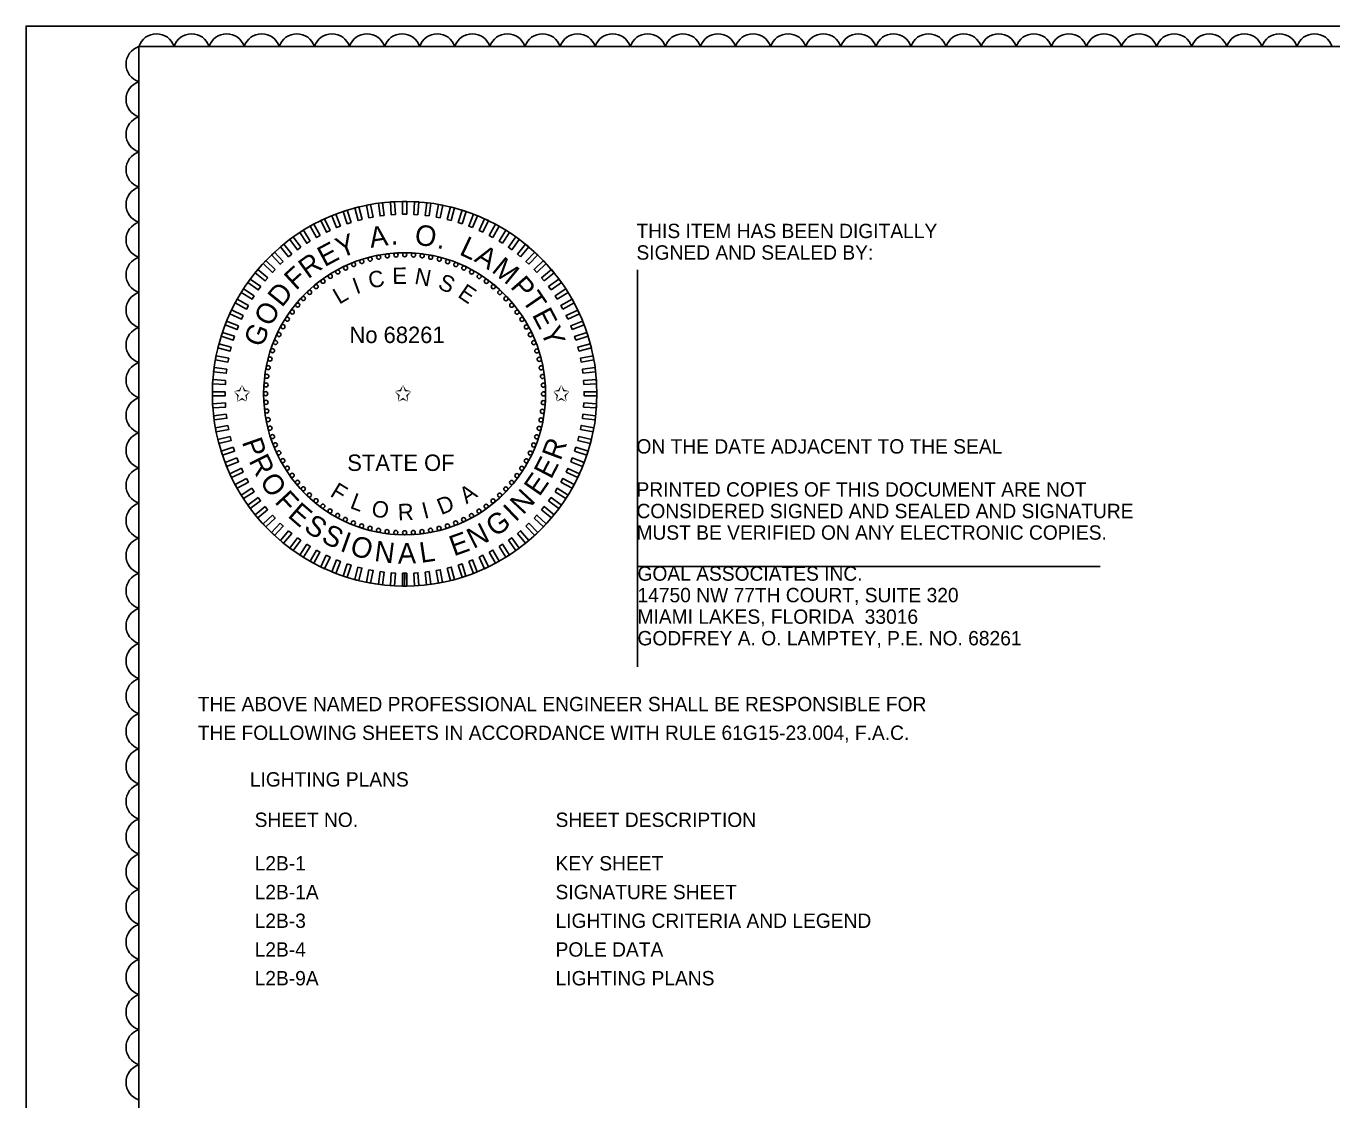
# Model space of a CAD drawing. Extents: x -811.3 to -790.1, y -2211.9 to -2188.9.
# Drawn here: x -811.34 to -804.97, y -2194.13 to -2188.9 of the extents above; entities that cross this region are included whole.
import ezdxf

# ---------------------------------------------------------------- set-up
doc = ezdxf.new("R2010")
doc.units = 0
for name, color, linetype in [('Cloud_dp', 7, 'Continuous'), ('Logo_dp', 7, 'Continuous'), ('NonPlottingEle_dp', 7, 'Continuous'), ('PlotBorder_dp', 7, 'Continuous'), ('ScratchEle_dp', 7, 'Continuous'), ('SheetBorder_dp', 7, 'Continuous'), ('TextMisc', 7, 'Continuous'), ('TextNotes', 7, 'Continuous')]:
    doc.layers.add(name, color=color, linetype=linetype)

msp = doc.modelspace()

# ---------------------------------------------------------------- linework, layer by layer
at = {"layer": 'Cloud_dp'}
for centre, start, end in [((-810.7002, -2189.0276), 17.5, 162.5), ((-810.5291, -2189.0276), 17.5, 162.5), ((-810.358, -2189.0276), 17.5, 162.5), ((-810.1868, -2189.0276), 17.5, 162.5), ((-810.0157, -2189.0276), 17.5, 162.5), ((-809.8446, -2189.0276), 17.5, 162.5), ((-809.6735, -2189.0276), 17.5, 162.5), ((-809.5024, -2189.0276), 17.5, 162.5), ((-809.3312, -2189.0276), 17.5, 162.5), ((-809.1601, -2189.0276), 17.5, 162.5), ((-808.989, -2189.0276), 17.5, 162.5), ((-808.8179, -2189.0276), 17.5, 162.5), ((-808.6467, -2189.0276), 17.5, 162.5), ((-808.4756, -2189.0276), 17.5, 162.5), ((-808.3045, -2189.0276), 17.5, 162.5), ((-808.1334, -2189.0276), 17.5, 162.5), ((-807.9622, -2189.0276), 17.5, 162.5), ((-807.7911, -2189.0276), 17.5, 162.5), ((-807.62, -2189.0276), 17.5, 162.5), ((-807.4489, -2189.0276), 17.5, 162.5), ((-807.2778, -2189.0276), 17.5, 162.5), ((-807.1066, -2189.0276), 17.5, 162.5), ((-806.9355, -2189.0276), 17.5, 162.5), ((-806.7644, -2189.0276), 17.5, 162.5), ((-806.5933, -2189.0276), 17.5, 162.5), ((-806.4221, -2189.0276), 17.5, 162.5), ((-806.251, -2189.0276), 17.5, 162.5), ((-806.0799, -2189.0276), 17.5, 162.5), ((-805.9088, -2189.0276), 17.5, 162.5), ((-805.7377, -2189.0276), 17.5, 162.5), ((-805.5665, -2189.0276), 17.5, 162.5), ((-805.3954, -2189.0276), 17.5, 162.5), ((-805.2243, -2189.0276), 17.5, 162.5), ((-805.0532, -2189.0276), 17.5, 162.5), ((-810.7588, -2189.0862), 107.5, 252.5), ((-810.7588, -2189.2573), 107.5, 252.5), ((-810.7588, -2189.4284), 107.5, 252.5), ((-810.7588, -2189.5996), 107.5, 252.5), ((-810.7588, -2189.7707), 107.5, 252.5), ((-810.7588, -2189.9418), 107.5, 252.5), ((-810.7588, -2190.1129), 107.5, 252.5), ((-810.7588, -2190.2841), 107.5, 252.5), ((-810.7588, -2190.4552), 107.5, 252.5), ((-810.7588, -2190.6263), 107.5, 252.5), ((-810.7588, -2190.7974), 107.5, 252.5), ((-810.7588, -2190.9685), 107.5, 252.5), ((-810.7588, -2191.1397), 107.5, 252.5), ((-810.7588, -2191.3108), 107.5, 252.5), ((-810.7588, -2191.4819), 107.5, 252.5), ((-810.7588, -2191.653), 107.5, 252.5), ((-810.7588, -2191.8242), 107.5, 252.5), ((-810.7588, -2191.9953), 107.5, 252.5), ((-810.7588, -2192.1664), 107.5, 252.5), ((-810.7588, -2192.3375), 107.5, 252.5), ((-810.7588, -2192.5087), 107.5, 252.5), ((-810.7588, -2192.6798), 107.5, 252.5), ((-810.7588, -2192.8509), 107.5, 252.5), ((-810.7588, -2193.022), 107.5, 252.5), ((-810.7588, -2193.1931), 107.5, 252.5), ((-810.7588, -2193.3643), 107.5, 252.5), ((-810.7588, -2193.5354), 107.5, 252.5), ((-810.7588, -2193.7065), 107.5, 252.5), ((-810.7588, -2193.8776), 107.5, 252.5), ((-810.7588, -2194.0488), 107.5, 252.5)]:
    msp.add_arc(centre, 0.0897, start, end, dxfattribs=at)
at = {"layer": 'Logo_dp'}
for p, q in [((-809.5001, -2191.6301), (-809.5003, -2191.5676)), ((-809.4901, -2191.6301), (-809.4903, -2191.5676)), ((-809.4801, -2191.6301), (-809.4803, -2191.5676))]:
    msp.add_line(p, q, dxfattribs=at)
for points in [[(-809.6979, -2189.8425), (-809.7174, -2189.8475), (-809.7329, -2189.7871), (-809.7134, -2189.782)], [(-809.6441, -2189.8312), (-809.6639, -2189.8349), (-809.6756, -2189.7736), (-809.6558, -2189.7698)], [(-809.5897, -2189.8232), (-809.6097, -2189.8257), (-809.6175, -2189.7638), (-809.5975, -2189.7612)], [(-809.5349, -2189.8187), (-809.555, -2189.8199), (-809.559, -2189.7576), (-809.5388, -2189.7563)], [(-809.4799, -2189.8176), (-809.5001, -2189.8176), (-809.5001, -2189.7551), (-809.4799, -2189.7551)], [(-809.425, -2189.8199), (-809.4452, -2189.8187), (-809.4412, -2189.7563), (-809.4211, -2189.7576)], [(-809.3703, -2189.8257), (-809.3904, -2189.8232), (-809.3825, -2189.7613), (-809.3625, -2189.7638)], [(-809.3162, -2189.835), (-809.336, -2189.8312), (-809.3243, -2189.7699), (-809.3045, -2189.7736)], [(-809.2626, -2189.8476), (-809.2822, -2189.8426), (-809.2667, -2189.7821), (-809.2471, -2189.7871)], [(-809.8535, -2189.8965), (-809.8717, -2189.9051), (-809.8983, -2189.8486), (-809.8801, -2189.84)], [(-809.8028, -2189.8753), (-809.8215, -2189.8827), (-809.8445, -2189.8246), (-809.8258, -2189.8172)], [(-809.7508, -2189.8572), (-809.77, -2189.8635), (-809.7893, -2189.8041), (-809.7701, -2189.7979)], [(-809.21, -2189.8635), (-809.2292, -2189.8573), (-809.2099, -2189.7979), (-809.1907, -2189.8042)], [(-809.1585, -2189.8828), (-809.1773, -2189.8753), (-809.1543, -2189.8173), (-809.1355, -2189.8247)], [(-809.1083, -2189.9052), (-809.1266, -2189.8966), (-809.1, -2189.8401), (-809.0817, -2189.8487)], [(-809.9504, -2189.9483), (-809.9674, -2189.9591), (-810.0009, -2189.9064), (-809.9838, -2189.8956)], [(-809.9027, -2189.9209), (-809.9204, -2189.9306), (-809.9505, -2189.8759), (-809.9328, -2189.8662)], [(-809.0596, -2189.9307), (-809.0773, -2189.921), (-809.0473, -2189.8663), (-809.0296, -2189.876)], [(-809.0127, -2189.9592), (-809.0297, -2189.9484), (-808.9962, -2189.8957), (-808.9792, -2189.9065)], [(-810.04, -2190.0119), (-810.0556, -2190.0247), (-810.0954, -2189.9766), (-810.0798, -2189.9638)], [(-809.9962, -2189.9787), (-810.0125, -2189.9906), (-810.0492, -2189.94), (-810.0329, -2189.9282)], [(-808.9676, -2189.9907), (-808.9839, -2189.9788), (-808.9472, -2189.9283), (-808.9308, -2189.9402)], [(-808.9245, -2190.0249), (-808.9401, -2190.012), (-808.9003, -2189.9639), (-808.8847, -2189.9768)], [(-810.0817, -2190.0478), (-810.0964, -2190.0616), (-810.1392, -2190.0161), (-810.1244, -2190.0022)], [(-808.8837, -2190.0617), (-808.8984, -2190.0479), (-808.8557, -2190.0024), (-808.841, -2190.0162)], [(-810.1579, -2190.127), (-810.1707, -2190.1425), (-810.2188, -2190.1027), (-810.206, -2190.0872)], [(-810.121, -2190.0862), (-810.1348, -2190.1009), (-810.1804, -2190.0581), (-810.1665, -2190.0434)], [(-808.8453, -2190.101), (-808.8591, -2190.0863), (-808.8136, -2190.0436), (-808.7998, -2190.0583)], [(-808.8094, -2190.1427), (-808.8223, -2190.1271), (-808.7742, -2190.0873), (-808.7613, -2190.1029)], [(-810.192, -2190.17), (-810.2039, -2190.1864), (-810.2544, -2190.1497), (-810.2426, -2190.1333)], [(-808.7762, -2190.1865), (-808.7881, -2190.1702), (-808.7376, -2190.1335), (-808.7257, -2190.1498)], [(-810.252, -2190.2621), (-810.2617, -2190.2798), (-810.3164, -2190.2497), (-810.3067, -2190.232)], [(-810.2235, -2190.2151), (-810.2343, -2190.2322), (-810.287, -2190.1987), (-810.2762, -2190.1817)], [(-808.7459, -2190.2323), (-808.7567, -2190.2153), (-808.7039, -2190.1818), (-808.6931, -2190.1989)], [(-808.7184, -2190.28), (-808.7281, -2190.2623), (-808.6734, -2190.2322), (-808.6637, -2190.2499)], [(-810.2775, -2190.3108), (-810.2861, -2190.3291), (-810.3426, -2190.3025), (-810.334, -2190.2842)], [(-808.694, -2190.3292), (-808.7026, -2190.311), (-808.6461, -2190.2844), (-808.6375, -2190.3027)], [(-810.3, -2190.361), (-810.3074, -2190.3798), (-810.3654, -2190.3568), (-810.358, -2190.338)], [(-808.6728, -2190.3799), (-808.6802, -2190.3612), (-808.6222, -2190.3382), (-808.6147, -2190.357)], [(-810.3192, -2190.4125), (-810.3254, -2190.4317), (-810.3848, -2190.4124), (-810.3786, -2190.3932)], [(-808.6548, -2190.4319), (-808.661, -2190.4127), (-808.6016, -2190.3934), (-808.5954, -2190.4126)], [(-810.3351, -2190.4651), (-810.3401, -2190.4847), (-810.4006, -2190.4691), (-810.3956, -2190.4496)], [(-808.64, -2190.4849), (-808.6451, -2190.4653), (-808.5846, -2190.4498), (-808.5796, -2190.4693)], [(-810.3477, -2190.5186), (-810.3515, -2190.5385), (-810.4129, -2190.5268), (-810.4091, -2190.5069)], [(-808.6287, -2190.5386), (-808.6325, -2190.5188), (-808.5711, -2190.5071), (-808.5673, -2190.5269)], [(-810.357, -2190.5728), (-810.3595, -2190.5928), (-810.4215, -2190.585), (-810.4189, -2190.565)], [(-808.6207, -2190.593), (-808.6232, -2190.573), (-808.5613, -2190.5652), (-808.5588, -2190.5852)], [(-810.3628, -2190.6275), (-810.3641, -2190.6476), (-810.4264, -2190.6437), (-810.4251, -2190.6236)], [(-808.6162, -2190.6478), (-808.6174, -2190.6277), (-808.5551, -2190.6238), (-808.5539, -2190.6439)], [(-810.3652, -2190.6824), (-810.3652, -2190.7026), (-810.4276, -2190.7026), (-810.4276, -2190.6824)], [(-810.3641, -2190.7374), (-810.3628, -2190.7575), (-810.4251, -2190.7614), (-810.4264, -2190.7413)], [(-808.6175, -2190.7577), (-808.6162, -2190.7376), (-808.5539, -2190.7415), (-808.5551, -2190.7616)], [(-808.6151, -2190.7028), (-808.6151, -2190.6826), (-808.5527, -2190.6826), (-808.5527, -2190.7028)], [(-810.3595, -2190.7922), (-810.357, -2190.8122), (-810.4189, -2190.82), (-810.4215, -2190.8)], [(-808.6233, -2190.8124), (-808.6207, -2190.7923), (-808.5588, -2190.8002), (-808.5613, -2190.8202)], [(-810.3516, -2190.8466), (-810.3478, -2190.8664), (-810.4091, -2190.8781), (-810.4129, -2190.8583)], [(-808.6325, -2190.8666), (-808.6287, -2190.8467), (-808.5674, -2190.8584), (-808.5712, -2190.8783)], [(-810.3402, -2190.9003), (-810.3352, -2190.9199), (-810.3957, -2190.9354), (-810.4007, -2190.9159)], [(-808.6451, -2190.9201), (-808.6401, -2190.9005), (-808.5796, -2190.916), (-808.5846, -2190.9356)], [(-810.3255, -2190.9533), (-810.3192, -2190.9725), (-810.3786, -2190.9918), (-810.3849, -2190.9726)], [(-808.6611, -2190.9727), (-808.6548, -2190.9535), (-808.5954, -2190.9728), (-808.6017, -2190.992)], [(-810.3075, -2191.0052), (-810.3, -2191.024), (-810.3581, -2191.047), (-810.3655, -2191.0282)], [(-810.2862, -2191.0559), (-810.2776, -2191.0742), (-810.3341, -2191.1008), (-810.3427, -2191.0825)], [(-808.7027, -2191.0744), (-808.6941, -2191.0561), (-808.6376, -2191.0827), (-808.6462, -2191.101)], [(-808.6803, -2191.0242), (-808.6729, -2191.0054), (-808.6148, -2191.0284), (-808.6222, -2191.0472)], [(-810.2618, -2191.1052), (-810.2521, -2191.1229), (-810.3068, -2191.153), (-810.3165, -2191.1353)], [(-808.7282, -2191.1231), (-808.7185, -2191.1054), (-808.6638, -2191.1355), (-808.6735, -2191.1532)], [(-810.2344, -2191.1529), (-810.2236, -2191.1699), (-810.2763, -2191.2034), (-810.2871, -2191.1863)], [(-808.7568, -2191.1701), (-808.746, -2191.153), (-808.6932, -2191.1865), (-808.704, -2191.2035)], [(-810.204, -2191.1987), (-810.1922, -2191.215), (-810.2427, -2191.2517), (-810.2545, -2191.2354)], [(-810.1708, -2191.2425), (-810.158, -2191.2581), (-810.2061, -2191.2979), (-810.2189, -2191.2823)], [(-808.8224, -2191.2582), (-808.8095, -2191.2427), (-808.7614, -2191.2825), (-808.7743, -2191.298)], [(-808.7882, -2191.2152), (-808.7763, -2191.1988), (-808.7258, -2191.2355), (-808.7377, -2191.2519)], [(-810.135, -2191.2842), (-810.1211, -2191.2989), (-810.1667, -2191.3416), (-810.1805, -2191.3269)], [(-808.8592, -2191.299), (-808.8454, -2191.2843), (-808.7999, -2191.327), (-808.8137, -2191.3418)], [(-810.0965, -2191.3235), (-810.0818, -2191.3373), (-810.1246, -2191.3828), (-810.1393, -2191.369)], [(-810.0557, -2191.3603), (-810.0402, -2191.3732), (-810.08, -2191.4213), (-810.0955, -2191.4084)], [(-808.9402, -2191.3733), (-808.9247, -2191.3604), (-808.8848, -2191.4086), (-808.9004, -2191.4214)], [(-808.8985, -2191.3374), (-808.8838, -2191.3236), (-808.8411, -2191.3691), (-808.8558, -2191.383)], [(-810.0127, -2191.3945), (-809.9964, -2191.4064), (-810.0331, -2191.4569), (-810.0494, -2191.445)], [(-809.9676, -2191.426), (-809.9505, -2191.4368), (-809.984, -2191.4895), (-810.001, -2191.4787)], [(-809.0299, -2191.4369), (-809.0128, -2191.4261), (-808.9794, -2191.4788), (-808.9964, -2191.4896)], [(-808.984, -2191.4065), (-808.9677, -2191.3946), (-808.931, -2191.4451), (-808.9473, -2191.457)], [(-809.9206, -2191.4545), (-809.9029, -2191.4642), (-809.933, -2191.5189), (-809.9507, -2191.5092)], [(-809.8719, -2191.48), (-809.8536, -2191.4886), (-809.8802, -2191.5451), (-809.8985, -2191.5365)], [(-809.8217, -2191.5024), (-809.8029, -2191.5099), (-809.8259, -2191.5679), (-809.8447, -2191.5605)], [(-809.1775, -2191.5099), (-809.1587, -2191.5025), (-809.1357, -2191.5606), (-809.1545, -2191.568)], [(-809.1268, -2191.4887), (-809.1085, -2191.4801), (-809.0819, -2191.5366), (-809.1002, -2191.5452)], [(-809.0775, -2191.4643), (-809.0598, -2191.4546), (-809.0297, -2191.5093), (-809.0474, -2191.519)], [(-809.7702, -2191.5217), (-809.751, -2191.5279), (-809.7703, -2191.5873), (-809.7895, -2191.581)], [(-809.7176, -2191.5376), (-809.698, -2191.5426), (-809.7136, -2191.6031), (-809.7331, -2191.5981)], [(-809.6641, -2191.5502), (-809.6443, -2191.554), (-809.656, -2191.6153), (-809.6758, -2191.6116)], [(-809.6099, -2191.5594), (-809.5899, -2191.562), (-809.5977, -2191.6239), (-809.6177, -2191.6214)], [(-809.5552, -2191.5653), (-809.5351, -2191.5665), (-809.539, -2191.6288), (-809.5592, -2191.6276)], [(-809.5003, -2191.5676), (-809.4801, -2191.5676), (-809.4801, -2191.6301), (-809.5003, -2191.6301)], [(-809.4453, -2191.5665), (-809.4252, -2191.5653), (-809.4213, -2191.6276), (-809.4414, -2191.6289)], [(-809.3906, -2191.562), (-809.3705, -2191.5595), (-809.3627, -2191.6214), (-809.3827, -2191.624)], [(-809.3362, -2191.554), (-809.3163, -2191.5503), (-809.3046, -2191.6116), (-809.3245, -2191.6154)], [(-809.2824, -2191.5427), (-809.2628, -2191.5376), (-809.2473, -2191.5981), (-809.2668, -2191.6031)], [(-809.2294, -2191.5279), (-809.2102, -2191.5217), (-809.1909, -2191.5811), (-809.2101, -2191.5873)]]:
    msp.add_lwpolyline(points, close=True, dxfattribs=at)
for centre in [(-809.6989, -2190.0481), (-809.6581, -2190.0363), (-809.6165, -2190.027), (-809.5745, -2190.0204), (-809.5321, -2190.0164), (-809.4896, -2190.0151), (-809.447, -2190.0165), (-809.4047, -2190.0205), (-809.3626, -2190.0272), (-809.3211, -2190.0366), (-809.2802, -2190.0485), (-809.816, -2190.0987), (-809.7781, -2190.0794), (-809.739, -2190.0625), (-809.2402, -2190.0629), (-809.2012, -2190.0798), (-809.1633, -2190.0992), (-809.9215, -2190.1702), (-809.8879, -2190.1442), (-809.8527, -2190.1203), (-809.1266, -2190.1209), (-809.0915, -2190.1448), (-809.0579, -2190.171), (-809.9836, -2190.2284), (-809.9535, -2190.1984), (-809.026, -2190.1991), (-808.9959, -2190.2292), (-810.0379, -2190.2939), (-810.0118, -2190.2603), (-808.9678, -2190.2612), (-808.9417, -2190.2948), (-810.0835, -2190.3657), (-810.0618, -2190.3291), (-808.9178, -2190.3301), (-808.8962, -2190.3667), (-810.1029, -2190.4036), (-808.8769, -2190.4047), (-810.1343, -2190.4827), (-810.1198, -2190.4427), (-808.86, -2190.4437), (-808.8456, -2190.4838), (-810.1462, -2190.5236), (-808.8338, -2190.5247), (-810.1622, -2190.6071), (-810.1555, -2190.5651), (-808.8245, -2190.5662), (-808.8179, -2190.6082), (-810.1662, -2190.6495), (-808.814, -2190.6506), (-810.1676, -2190.692), (-810.1663, -2190.7346), (-808.814, -2190.7357), (-808.8127, -2190.6932), (-810.1623, -2190.7769), (-808.8181, -2190.7781), (-810.1557, -2190.819), (-810.1464, -2190.8605), (-808.8341, -2190.8616), (-808.8248, -2190.8201), (-810.1346, -2190.9014), (-810.1202, -2190.9415), (-808.8604, -2190.9425), (-808.846, -2190.9025), (-810.1034, -2190.9805), (-808.8774, -2190.9816), (-810.0841, -2191.0185), (-810.0624, -2191.0551), (-808.9184, -2191.0561), (-808.8967, -2191.0195), (-810.0385, -2191.0903), (-810.0125, -2191.124), (-808.9685, -2191.1249), (-808.9424, -2191.0913), (-809.9844, -2191.1559), (-809.9543, -2191.1861), (-809.0268, -2191.1868), (-808.9967, -2191.1568), (-809.9224, -2191.2142), (-809.8888, -2191.2403), (-809.0924, -2191.241), (-809.0587, -2191.215), (-809.8536, -2191.2643), (-809.817, -2191.286), (-809.7791, -2191.3053), (-809.74, -2191.3223), (-809.2413, -2191.3227), (-809.2022, -2191.3058), (-809.1642, -2191.2865), (-809.1276, -2191.2649), (-809.7, -2191.3367), (-809.6591, -2191.3486), (-809.6176, -2191.358), (-809.5756, -2191.3647), (-809.5332, -2191.3687), (-809.4901, -2191.3701), (-809.4481, -2191.3688), (-809.4058, -2191.3648), (-809.3637, -2191.3582), (-809.3222, -2191.3489), (-809.2813, -2191.3371)]:
    msp.add_circle(centre, 0.01, dxfattribs=at)
at = {"layer": 'NonPlottingEle_dp'}
for radius in [0.9375, 0.6875]:
    msp.add_circle((-809.4901, -2190.6926), radius, dxfattribs=at)
at = {"layer": 'PlotBorder_dp'}
msp.add_lwpolyline([(-811.3358, -2199.5006), (-794.8358, -2199.5006), (-794.8358, -2188.9006), (-811.3358, -2188.9006)], close=True, dxfattribs=at)
at = {"layer": 'ScratchEle_dp'}
for p, q in [((-808.3546, -2190.0892), (-808.3546, -2192.0239)), ((-808.3546, -2191.5339), (-806.0979, -2191.5339))]:
    msp.add_line(p, q, dxfattribs=at)
at = {"layer": 'SheetBorder_dp'}
for q in [(-810.7858, -2199.4006), (-795.3858, -2189.0006)]:
    msp.add_line((-810.7858, -2189.0006), q, dxfattribs=at)

# ---------------------------------------------------------------- texts
at = {"layer": 'Logo_dp'}
for s, height, rotation, p in [('Y', 0.1, 21.06329, (-809.8021, -2190.0332)), ('A', 0.1, 8.80884, (-809.6551, -2189.982)), ('O', 0.1, 352.18771, (-809.4449, -2189.9645)), ('E', 0.1, 28.10553, (-809.8806, -2190.0764)), ('.', 0.1, 1.04184, (-809.5575, -2189.9662)), ('.', 0.1, 343.52684, (-809.3358, -2189.9796)), ('L', 0.1, 334.67271, (-809.2279, -2190.0118)), ('R', 0.1, 35.92688, (-809.9609, -2190.1353)), ('A', 0.1, 328.40959, (-809.1552, -2190.0445)), ('M', 0.1, 320.6426, (-809.0707, -2190.0957)), ('F', 0.1, 42.37723, (-810.0205, -2190.1917)), ('C', 0.08, 12.20255, (-809.6579, -2190.181)), ('E', 0.08, 0.41861, (-809.5498, -2190.1575)), ('N', 0.08, 349.29143, (-809.4455, -2190.1561)), ('D', 0.1, 50.8569, (-810.0886, -2190.2754)), ('I', 0.08, 20.01168, (-809.7258, -2190.2085)), ('S', 0.08, 337.02207, (-809.3325, -2190.1778)), ('E', 0.08, 325.86633, (-809.2358, -2190.218)), ('P', 0.1, 311.19658, (-808.9784, -2190.1727)), ('L', 0.08, 30.40215, (-809.8093, -2190.259)), ('T', 0.1, 304.45632, (-808.9209, -2190.2363)), ('O', 0.1, 59.51777, (-810.1446, -2190.3702)), ('E', 0.1, 297.63152, (-808.8707, -2190.3072)), ('G', 0.1, 68.0518, (-810.1851, -2190.4709)), ('Y', 0.1, 290.58928, (-808.8281, -2190.386)), ('P', 0.1, 289.40551, (-810.2848, -2190.9272)), ('R', 0.1, 69.5134, (-808.7299, -2191.0223)), ('R', 0.1, 296.14576, (-810.2518, -2191.0188)), ('E', 0.1, 62.47116, (-808.7761, -2191.113)), ('O', 0.1, 303.96711, (-810.2003, -2191.1194)), ('E', 0.1, 55.42892, (-808.833, -2191.1974)), ('F', 0.1, 312.62798, (-810.1279, -2191.2215)), ('F', 0.08, 328.72408, (-809.8582, -2191.1892)), ('L', 0.08, 339.29159, (-809.7609, -2191.2483)), ('A', 0.08, 34.49917, (-809.1883, -2191.232)), ('N', 0.1, 47.17876, (-808.9123, -2191.2864)), ('E', 0.1, 319.07833, (-810.0645, -2191.2898)), ('O', 0.08, 349.68206, (-809.6562, -2191.288)), ('R', 0.08, 2.33977, (-809.5217, -2191.3099)), ('I', 0.08, 14.20366, (-809.3941, -2191.3032)), ('D', 0.08, 22.01279, (-809.312, -2191.2845)), ('I', 0.1, 43.64556, (-808.9499, -2191.3209)), ('S', 0.1, 326.12056, (-809.9869, -2191.3557)), ('G', 0.1, 35.11153, (-809.0492, -2191.3941)), ('S', 0.1, 333.193, (-809.9015, -2191.4119)), ('I', 0.1, 340.26543, (-809.8098, -2191.457)), ('E', 0.1, 19.81912, (-809.2498, -2191.4856)), ('N', 0.1, 26.86136, (-809.1544, -2191.4501)), ('O', 0.1, 343.79863, (-809.7621, -2191.4753)), ('N', 0.1, 352.45949, (-809.6411, -2191.5073)), ('A', 0.1, 0.70966, (-809.5227, -2191.5206)), ('L', 0.1, 8.47665, (-809.4105, -2191.5174))]:
    msp.add_text(s, height=height, rotation=rotation, dxfattribs=at).set_placement(p)
for s, p in [('No 68261', (-809.7591, -2190.4454)), ('✩', (-810.3251, -2190.7305)), ('✩', (-809.5404, -2190.7305)), ('✩', (-808.7685, -2190.7305)), ('STATE OF', (-809.7698, -2191.0688))]:
    msp.add_text(s, height=0.08, dxfattribs=at).set_placement(p)
at = {"layer": 'TextMisc'}
for s, p in [('THIS ITEM HAS BEEN DIGITALLY', (-808.3596, -2189.934)), ('SIGNED AND SEALED BY:', (-808.3596, -2190.039)), ('ON THE DATE ADJACENT TO THE SEAL', (-808.3596, -2190.984)), ('PRINTED COPIES OF THIS DOCUMENT ARE NOT ', (-808.3596, -2191.194)), ('CONSIDERED SIGNED AND SEALED AND SIGNATURE ', (-808.3596, -2191.299)), ('MUST BE VERIFIED ON ANY ELECTRONIC COPIES.', (-808.3596, -2191.404)), ('GOAL ASSOCIATES INC.', (-808.3546, -2191.6039)), ('14750 NW 77TH COURT, SUITE 320', (-808.3546, -2191.7089)), ('MIAMI LAKES, FLORIDA  33016', (-808.3546, -2191.8139)), ('GODFREY A. O. LAMPTEY, P.E. NO. 68261', (-808.3546, -2191.9189)), ('THE ABOVE NAMED PROFESSIONAL ENGINEER SHALL BE RESPONSIBLE FOR ', (-810.4987, -2192.24)), ('THE FOLLOWING SHEETS IN ACCORDANCE WITH RULE 61G15-23.004, F.A.C.', (-810.4987, -2192.38)), ('LIGHTING PLANS', (-810.245, -2192.6071))]:
    msp.add_text(s, height=0.07, dxfattribs=at).set_placement(p)
at = {"layer": 'TextNotes'}
for s, p in [('SHEET NO.', (-810.2215, -2192.8041)), ('SHEET DESCRIPTION', (-808.7542, -2192.8041)), ('L2B-1', (-810.2215, -2193.0162)), ('KEY SHEET', (-808.7542, -2193.0162)), ('L2B-1A', (-810.2215, -2193.1562)), ('SIGNATURE SHEET', (-808.7542, -2193.1562)), ('L2B-3', (-810.2215, -2193.2962)), ('LIGHTING CRITERIA AND LEGEND', (-808.7542, -2193.2962)), ('L2B-4 ', (-810.2215, -2193.4362)), ('POLE DATA', (-808.7542, -2193.4362)), ('L2B-9A', (-810.2215, -2193.5762)), ('LIGHTING PLANS', (-808.7542, -2193.5762))]:
    msp.add_text(s, height=0.07, dxfattribs=at).set_placement(p)

doc.saveas('drawing.dxf')
